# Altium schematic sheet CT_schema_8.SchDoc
size 277 x 170 mm
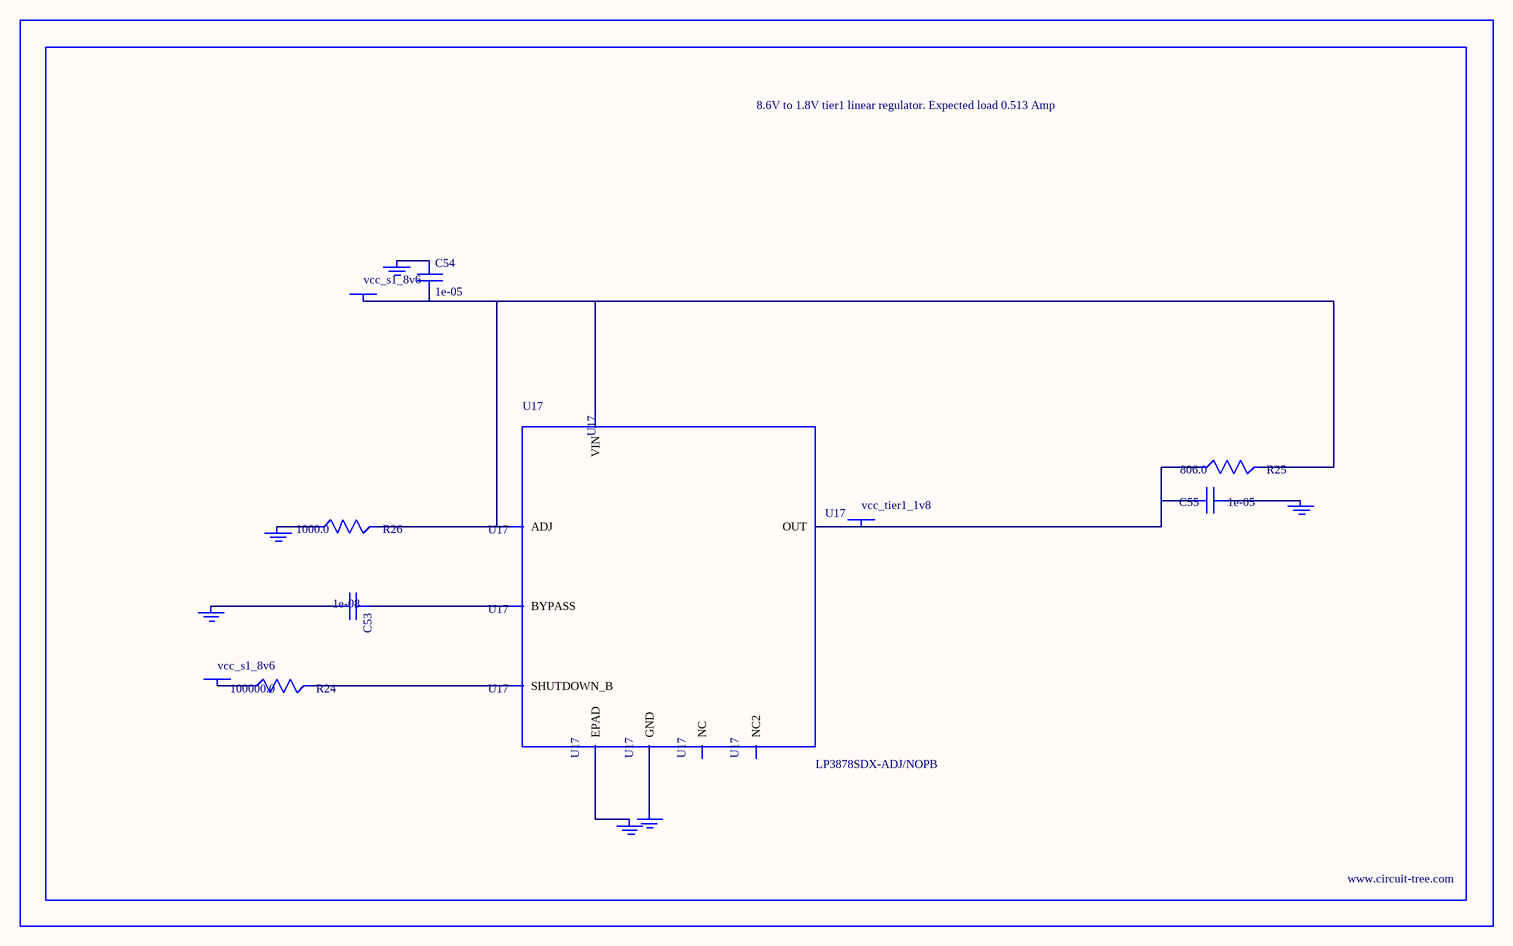
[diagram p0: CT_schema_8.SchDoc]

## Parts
BORDER7  (no value)
C53  1e-08  [C0402]
C54  1e-05  [C1206]
C55  1e-05  [C0805]
GND_INSTANCE_7_0  (no value)
GND_INSTANCE_7_1  (no value)
GND_INSTANCE_7_2  (no value)
GND_INSTANCE_7_3  (no value)
GND_INSTANCE_7_4  (no value)
GND_INSTANCE_7_5  (no value)
POWER_INSTANCE_7_0  vcc_s1_8v6
POWER_INSTANCE_7_1  vcc_s1_8v6
POWER_INSTANCE_7_2  vcc_tier1_1v8
R24  100000.0  [R0603]
R25  806.0  [R0603]
R26  1000.0  [R0603]
U17  LP3878SDX-ADJ/NOPB  [WSON-8]

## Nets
NetC53_1: C53.1 U17.1(BYPASS)
NetC53_2: C53.2 GND_INSTANCE_7_0.0(GND)
NetC54_1: C54.1 GND_INSTANCE_7_1.0(GND)
NetC54_2: C54.2 POWER_INSTANCE_7_0.0(PWR) R25.2 R26.2 U17.4(VIN) U17.6(ADJ)
NetC55_1: C55.1 GND_INSTANCE_7_2.0(GND)
NetC55_2: C55.2 POWER_INSTANCE_7_2.0(PWR) R25.1 U17.5(OUT)
NetGND_INSTANCE_7_3_0: GND_INSTANCE_7_3.0(GND) R26.1
NetGND_INSTANCE_7_4_0: GND_INSTANCE_7_4.0(GND) U17.PAD(EPAD)
NetGND_INSTANCE_7_5_0: GND_INSTANCE_7_5.0(GND) U17.3(GND)
NetPOWER_INSTANCE_7_1_0: POWER_INSTANCE_7_1.0(PWR) R24.1
NetR24_2: R24.2 U17.8(SHUTDOWN_B)

Not connected (* = marked no-connect by the designer): U17 2(NC) 7(NC2)

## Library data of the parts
BORDER7 = BORDER_PAGE7
C53 = C0402C103K3RAC
C54 = C1206C106K3RACTU
C55 = GRM219R60J106ME19D
GND_INSTANCE_7_0-GND_INSTANCE_7_5 = GND
POWER_INSTANCE_7_0-POWER_INSTANCE_7_2 = PWR
R24 = RC0603JR-07100KL
R25 = ERJ-3EKF8060V
R26 = RC0603JR-071KL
